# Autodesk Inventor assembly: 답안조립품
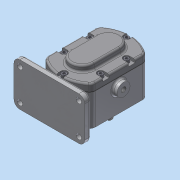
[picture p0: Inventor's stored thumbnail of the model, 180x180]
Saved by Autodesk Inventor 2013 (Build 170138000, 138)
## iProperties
Created: 2019-03
Part Number: 답안조립품
Document SubType Name: Assembly
Designer: dgall
Author: dgall
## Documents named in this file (11)
- C:\Users\dgall\Desktop\490307V1013\답안조립품.iam
- C:\Users\dgall\Desktop\490307V1013\본체.ipt
- C:\Users\dgall\Desktop\490307V1013\개스킷.ipt
- C:\Users\dgall\Desktop\490307V1013\메인축.ipt
- C:\Users\dgall\Desktop\490307V1013\베어링부시.ipt
- C:\Users\dgall\Desktop\490307V1013\볼트 M5.ipt
- C:\Users\dgall\Desktop\490307V1013\스퍼기어.ipt
- C:\Users\dgall\Desktop\490307V1013\오일 실 16 28 7.ipt
- C:\Users\dgall\Desktop\490307V1013\커버.ipt
- C:\Users\dgall\Desktop\490307V1013\키 6 x 6 x 18.ipt
- C:\Users\dgall\Desktop\490307V1013\서브축.ipt
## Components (1 placed, 1 different names)
1. 개스킷:1
